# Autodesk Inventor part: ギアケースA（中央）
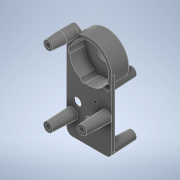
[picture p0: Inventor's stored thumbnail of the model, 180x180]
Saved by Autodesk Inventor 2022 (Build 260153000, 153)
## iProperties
Created: 2024-09
Part Number: ギアケースA（中央）
Material: ABS プラスチック
Document SubType Name: Modeling
Designer: neo09
Density: 1.06 g/cm^3
Appearance: 滑らか - 白
Author: neo09
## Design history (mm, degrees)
sketch "スケッチ2"
  geometry: L1 (-7.211, 43)-(-7, 43); L2 (14, 31)-(14, -10); L3 (10.5, -13.5)-(-10.5, -13.5); L4 (-14, -10)-(-14, 43); L5 (-8.152, 45.596)-(-6, 43.649); A1 r 3.5 centre (-10.5, 43) between (-7, 43) and (-7.002, 43.123); A2 r 3.5 centre (-10.5, 43) between (-8.152, 45.596) and (-14, 43); A3 r 14 centre (0, 31) between (14, 31) and (-6, 43.649); A4 r 14 centre (0, 31) between (-7.002, 43.123) and (-7.211, 43); A5 r 3.5 centre (-10.5, -10) between (-14, -10) and (-10.5, -13.5); A6 r 3.5 centre (10.5, -10) between (10.5, -13.5) and (14, -10); 2 further points
  constraints: 12 point on circle, 10 end point, 7 tangent, 6 centre point, 2 parallel, 2 point on line, 1 horizontal, 1 perpendicular, 1 vertical alignment
  dimensions: "d1" = 13.5 distance from line of point (0, 0) L3; "d2" = 43 distance from line of L1 point (0, 0); "d4" = 31 distance of point (0, 0) A3.centre; "d6" = 6 horizontal distance of point (0, 43) L5.end; "d7" = 3.5 radius of A5 (derived); "d8" = 3.5 radius of A6 (derived)
extrude "押し出し1" new body sketch "スケッチ2" distance "d9" = 2; taper "d10" = 0 deg
sketch "スケッチ3"
  geometry: L1 (-14, 43)-(-14, -10) reference; L2 (14, -10)-(14, 31) reference; C1 r 3.5 at (-10.5, -1); C2 r 3.5 at (10.5, 8); 1 further point
  constraints: 2 centre point, 2 tangent
  dimensions: "d11" = 7 diameter of C1; "d12" = 1 vertical distance of C1.centre point (0, 0); "d13" = 7 diameter of C2; "d14" = 8 vertical distance of point (0, 0) C2.centre
extrude "押し出し2" join sketch "スケッチ3" distance "d15" = 15; taper "d16" = -2.29 deg
sketch "スケッチ4"
  geometry: C1 r 3.5 at (-10.5, 43); A1 r 3.5 centre (-10.5, 43) between (-8.152, 45.596) and (-14, 43) reference; 1 further point
  constraints: 2 concentric, 1 centre point
extrude "押し出し3" join sketch "スケッチ4" distance "d17" = 7; taper "d18" = 0 deg
sketch "スケッチ5"
  geometry: C1 r 3.5 at (0, 0); 1 further point
  constraints: 1 centre point
extrude "押し出し4" join sketch "スケッチ5" distance "d19" = 8; taper "d20" = -4.29 deg
sketch "スケッチ6"
  geometry: L1 (-14, -10)-(-14, 31) reference; L2 (14, 43)-(14, -10) reference; C1 r 3.5 at (-10.5, 24); C2 r 3.5 at (10.5, 32); C3 r 3.5 at (-10.5, -10); C4 r 3.5 at (10.5, -10); A1 r 3.5 centre (-10.5, -10) between (-14, -10) and (-10.5, -13.5) reference; A2 r 3.5 centre (10.5, -10) between (10.5, -13.5) and (14, -10) reference; 5 further points
  constraints: 4 centre point, 2 coincident, 2 tangent
  dimensions: "d21" = 7 diameter of C1; "d22" = 24 vertical distance of point (0, 0) C1.centre; "d23" = 7 diameter of C2; "d24" = 32 vertical distance of point (0, 0) C2.centre
extrude "押し出し5" join sketch "スケッチ6" distance "d25" = 14; taper "d26" = -2.45 deg
sketch "スケッチ7"
  geometry: C1 r 1.5 at (0, 0); 1 further point
  constraints: 1 centre point
  dimensions: "d27" = 3 diameter of C1
extrude "押し出し6" cut sketch "スケッチ7" distance "d28" = 8.5; taper "d29" = 0 deg
sketch "スケッチ8"
  geometry: C1 r 1.5 at (0, 0); 1 further point
  constraints: 1 centre point
  dimensions: "d30" = 3 diameter of C1
extrude "押し出し7" cut sketch "スケッチ8" distance "d31" = 8.5; taper "d32" = 0 deg
sketch "スケッチ9"
  geometry: C1 r 1.5 at (0, 0); 1 further point
  constraints: 1 centre point
  dimensions: "d33" = 3 diameter of C1
extrude "押し出し8" cut sketch "スケッチ9" distance "d34" = 8.5; taper "d35" = 0 deg
feature "ねじ1" dims "d36" = 8.5, "d37" = 0
feature "ねじ2" dims "d38" = 8.5, "d39" = 0
feature "ねじ3" dims "d40" = 8.5, "d41" = 0
sketch "スケッチ10"
  geometry: C1 r 1.5 at (0, 0); 1 further point
  constraints: 1 centre point
  dimensions: "d42" = 3 diameter of C1
extrude "押し出し9" cut sketch "スケッチ10" distance "d43" = 5; taper "d44" = 0 deg
sketch "スケッチ11"
  geometry: C1 r 1.5 at (0, 0); 1 further point
  constraints: 1 centre point
  dimensions: "d45" = 3 diameter of C1
extrude "押し出し10" cut sketch "スケッチ11" distance "d46" = 8.5; taper "d47" = 0 deg
sketch "スケッチ12"
  geometry: C1 r 1.5 at (0, 0); 1 further point
  constraints: 1 centre point
  dimensions: "d48" = 3 diameter of C1
extrude "押し出し11" cut sketch "スケッチ12" distance "d49" = 8.5; taper "d50" = 0 deg
sketch "スケッチ13"
  geometry: C1 r 1.5 at (0, 0); 1 further point
  constraints: 1 centre point
  dimensions: "d51" = 3 diameter of C1
extrude "押し出し12" cut sketch "スケッチ13" distance "d52" = 8.5; taper "d53" = 0 deg
feature "ねじ4" dims "d54" = 5, "d55" = 0
feature "ねじ5" dims "d56" = 8.5, "d57" = 0
feature "ねじ6" dims "d58" = 8.5, "d59" = 0
feature "ねじ7" dims "d60" = 8.5, "d61" = 0
sketch "スケッチ14"
  geometry: C1 r 14 at (0, 31); A1 r 14 centre (0, 31) between (14, 31) and (-6, 43.649) reference; 1 further point
  constraints: 2 concentric, 1 centre point
extrude "押し出し13" join sketch "スケッチ14" distance "d62" = 11; taper "d63" = 0 deg
sketch "スケッチ15"
  geometry: C1 r 12 at (0, 31); A1 r 14 centre (0, 31) between (14, 31) and (-6, 43.649) reference; 1 further point
  constraints: 1 centre point, 1 concentric
  dimensions: "d64" = 24 diameter of C1
extrude "押し出し14" cut sketch "スケッチ15" distance "d65" = 9; taper "d66" = 0 deg
sketch "スケッチ17" dims "d74" = 25, "d75" = 25
  geometry: C1 r 11.5 at (-3.764, 11.92); C2 r 11 at (0, 31); C3 r 3 at (-3.764, 11.92); 3 further points
  constraints: 3 centre point, 1 coincident, 1 concentric, 6 other
  dimensions: "d76" = 6.5 vertical distance of point (0, 0) point (7.5, 6.5); "d77" = 7.5 horizontal distance of point (0, 0) point (7.5, 6.5); "d78" = 23 diameter of C1; "d79" = 22 diameter of C2; "d80" = 6 diameter of C3
extrude "押し出し15" join sketch "スケッチ17" distance "d81" = 5.3; taper "d82" = -5.4 deg
sketch "スケッチ18"
  geometry: C1 r 2.5 at (-10.5, 32); C2 r 2.5 at (10.5, 24); C3 r 1.5 at (-10.5, 32) reference; A1 r 1.5 centre (10.5, 24) between (11.98, 23.756) and (11.295, 22.728) reference; 1 further point
  constraints: 2 centre point, 2 concentric
  dimensions: "d83" = 5 diameter of C1; "d84" = 5 diameter of C2
extrude "押し出し16" cut sketch "スケッチ18" distance "d85" = 9; taper "d86" = 0 deg
sketch "スケッチ16" dims "d67" = 25, "d68" = 25, "d71" = 23, "d72" = 22
  geometry: C1 r 3 at (-3.764, 11.92); C2 r 2 at (3.723, 20.649); C3 r 2.5 at (0, 0); C4 r 2.5 at (7.5, 6.5); C5 r 1 at (-3.764, 11.92); C6 r 1 at (3.723, 20.649); C7 r 3.1 at (0, 31); A1 r 14 centre (0, 31) between (-9.769, 20.972) and (-13.014, 25.839) reference; 5 further points
  constraints: 7 centre point, 6 coincident, 14 other
  dimensions: "d69" = 6.5 vertical distance of point (0, 0) point (7.5, 6.5); "d70" = 7.5 horizontal distance of point (0, 0) point (7.5, 6.5); "d73" = 6 diameter of C1; "d87" = 4 diameter of C2; "d92" = 5 diameter of C3; "d93" = 5 diameter of C4; "d94" = 2 diameter of C5; "d95" = 2 diameter of C6; "d96" = 6.2 diameter of C7
extrude "押し出し17" cut sketch "スケッチ16" distance "d88" = 7; taper "d90" = 0 deg; dims "d89" = 2, "d91" = 0
extrude "押し出し18" cut sketch "スケッチ16" extent not by distance; stored distance "d97" = 14; taper "d98" = 0 deg
sketch "スケッチ19"
  geometry: C1 r 4.5 at (0, 0); C2 r 2.5 at (0, 0) reference; C3 r 4.5 at (7.5, 6.5); C4 r 2.5 at (7.5, 6.5) reference; 1 further point
  constraints: 2 centre point, 2 concentric
  dimensions: "d99" = 9 diameter of C1; "d100" = 9 diameter of C3
extrude "押し出し19" cut sketch "スケッチ19" distance "d101" = 1; taper "d102" = 0 deg
fillet "フィレット1" dims "d103" = 0.5
node "ソリッド1"
sketch "スケッチ1"
  geometry: 1 further point
other parameters: "d3" = 28, "d5" = 7
